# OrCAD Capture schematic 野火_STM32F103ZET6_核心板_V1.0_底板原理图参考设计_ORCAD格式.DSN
size A4; title: 野火_STM32F103ZET6底板参考设计_原理图; rev: V1.0; note: MCU_B2B
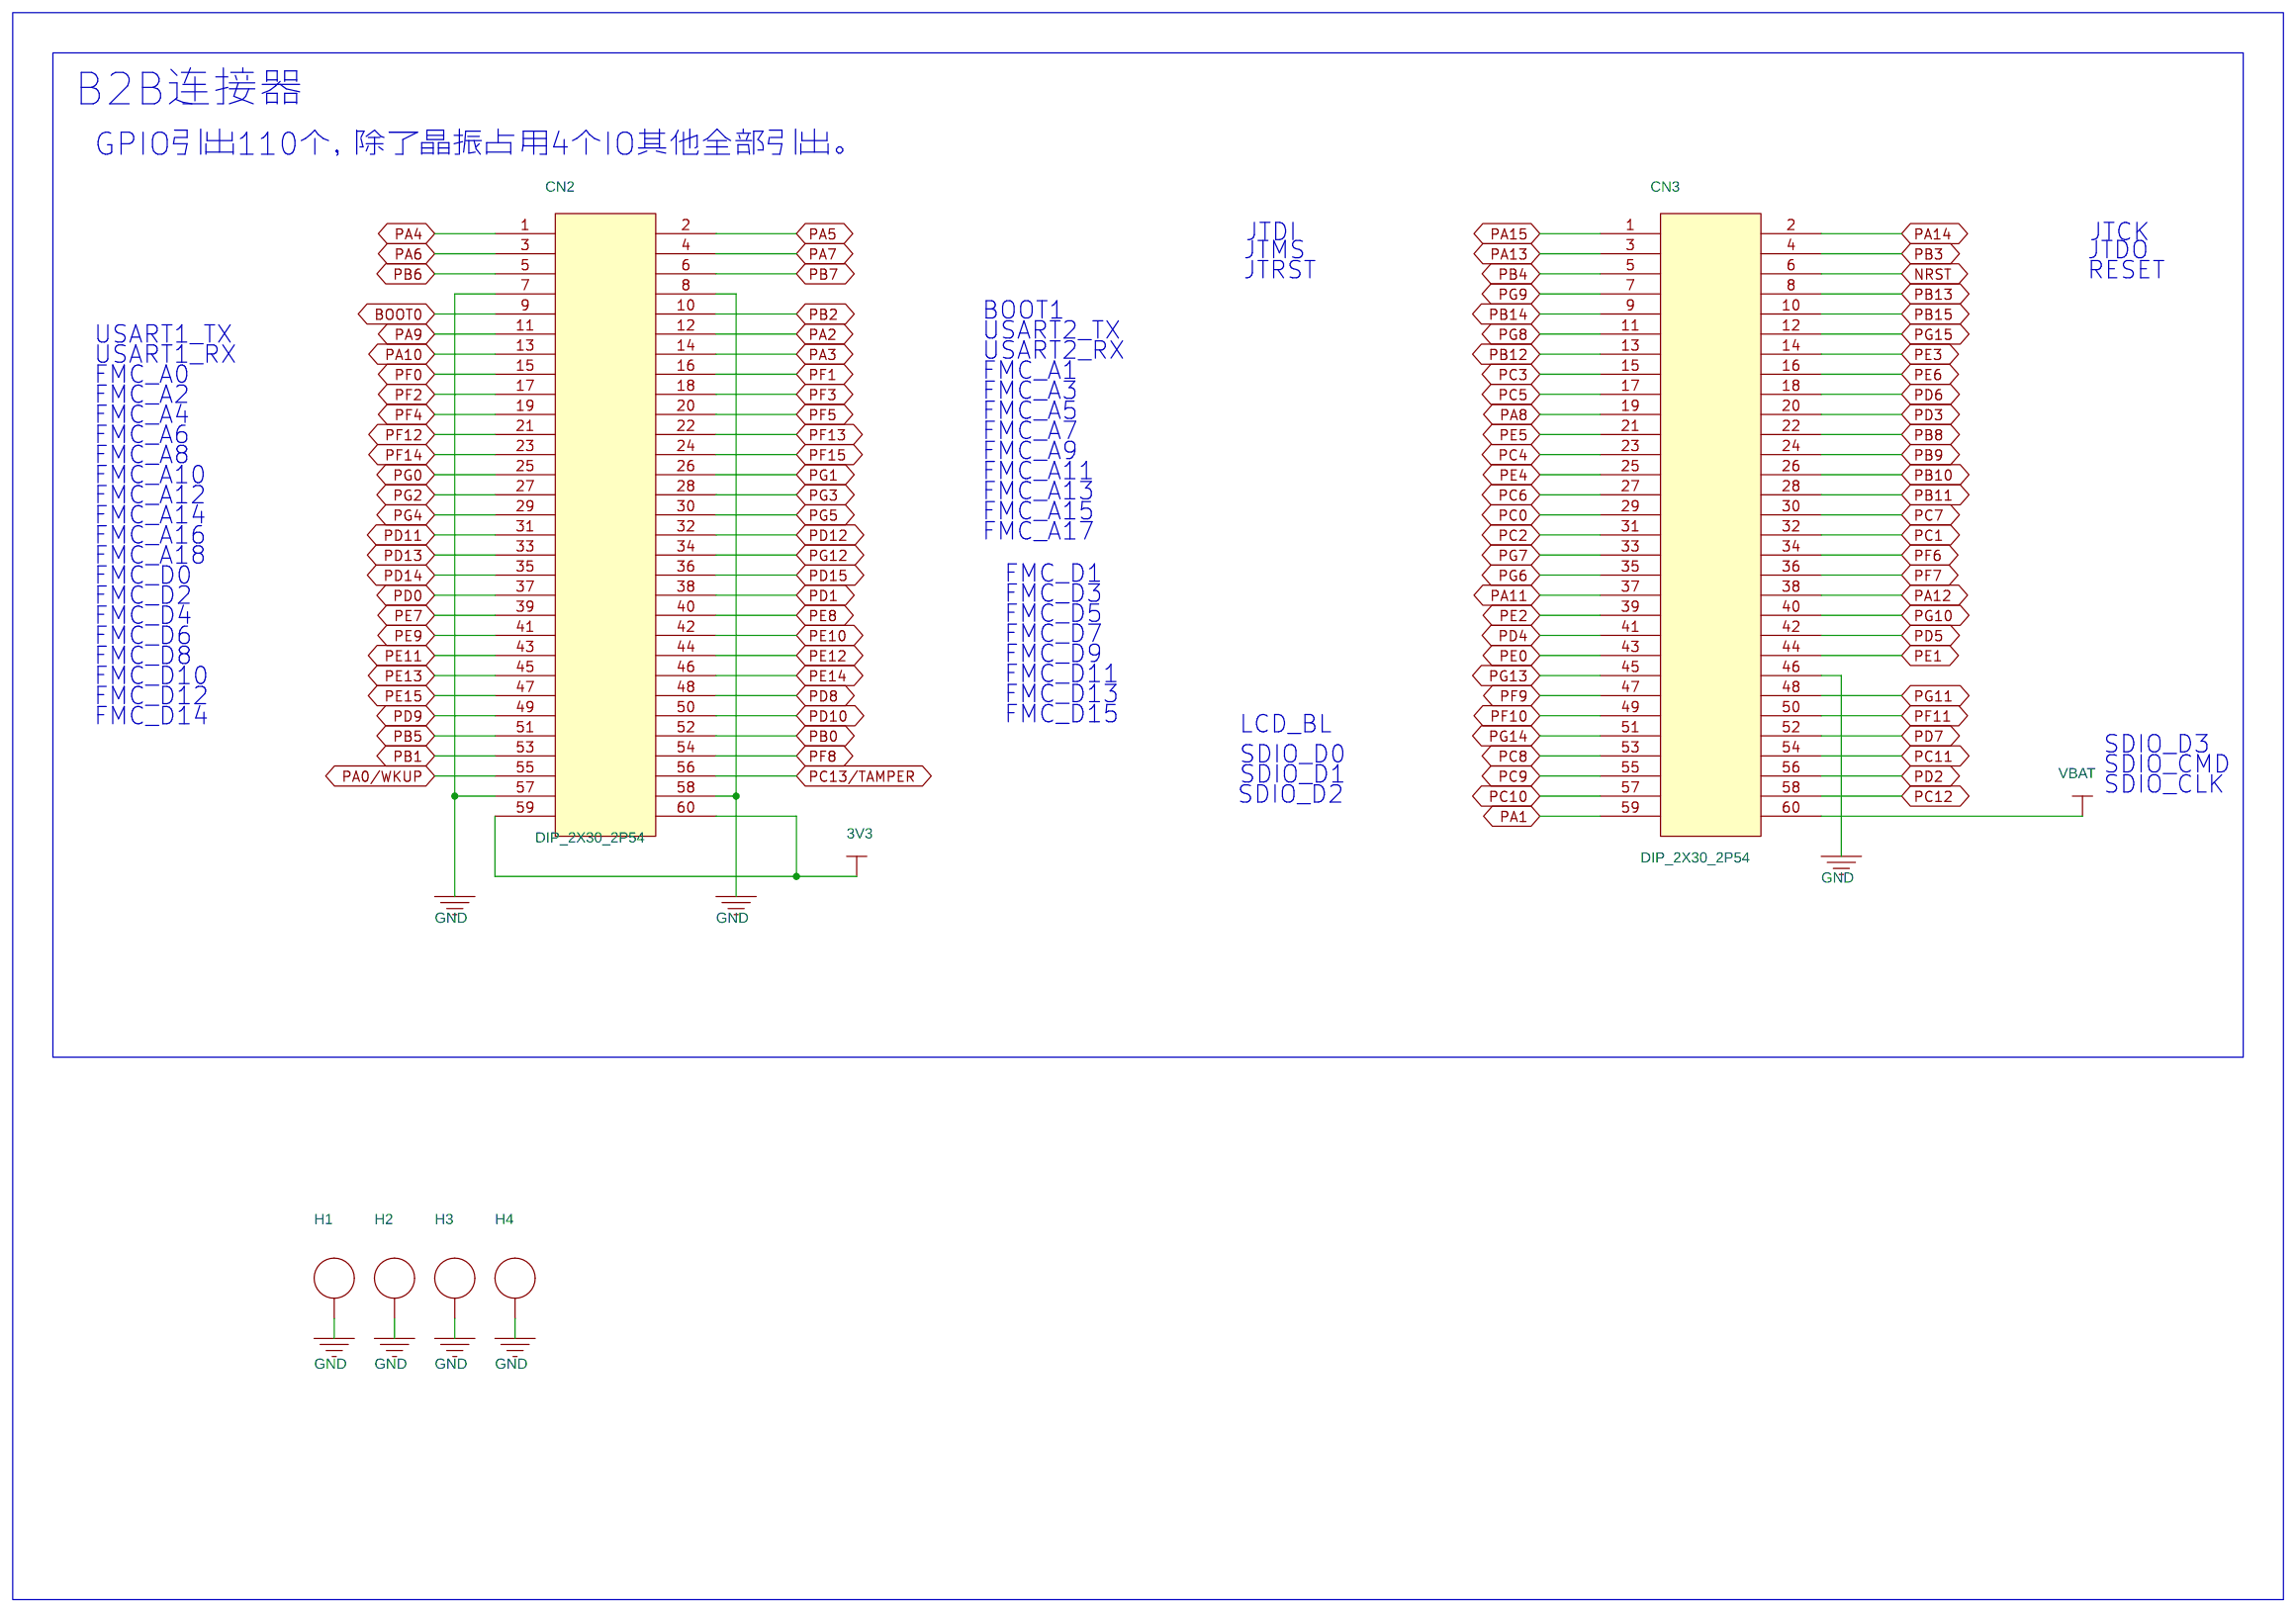
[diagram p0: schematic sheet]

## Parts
CN2  DIP_2X30_2P54  [DIP-2X302P54]
CN3  DIP_2X30_2P54  [DIP-2X302P54]
H1  3.0mm  [t3-5p5]
H2  3.0mm  [t3-5p5]
H3  3.0mm  [t3-5p5]
H4  3.0mm  [t3-5p5]

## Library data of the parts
CN2 CN3 = DIP_2X40_0
H1-H4 = SPACER_0: FASTENER, STANDOFF 4.5MMX3.53XM3.0X0.5 ROUND THR .635"L BRASS; AGILE_PN: 280-76498; ASSY_OPT: DNP; CAD_APPROVED: Yes; HEIGHT: 16.13MM; MFG_NAME01: UNICORP; MFG_PN01: MSS251-R-1-A-16; ROHS: Yes

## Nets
3V3: CN2.59 CN2.60
GND: CN2.7 CN2.8 CN2.57 CN2.58 CN3.46 H1.1(NC) H2.1(NC) H3.1(NC) H4.1(NC)
VBAT: CN3.60
BOOT0: CN2.9
NRST: CN3.6
PA0/WKUP: CN2.55
PA1: CN3.59
PA2: CN2.12
PA3: CN2.14
PA4: CN2.1
PA5: CN2.2
PA6: CN2.3
PA7: CN2.4
PA8: CN3.19
PA9: CN2.11
PA10: CN2.13
PA11: CN3.37
PA12: CN3.38
PA13: CN3.3
PA14: CN3.2
PA15: CN3.1
PB0: CN2.52
PB1: CN2.53
PB2: CN2.10
PB3: CN3.4
PB4: CN3.5
PB5: CN2.51
PB6: CN2.5
PB7: CN2.6
PB8: CN3.22
PB9: CN3.24
PB10: CN3.26
PB11: CN3.28
PB12: CN3.13
PB13: CN3.8
PB14: CN3.9
PB15: CN3.10
PC0: CN3.29
PC1: CN3.32
PC2: CN3.31
PC3: CN3.15
PC4: CN3.23
PC5: CN3.17
PC6: CN3.27
PC7: CN3.30
PC8: CN3.53
PC9: CN3.55
PC10: CN3.57
PC11: CN3.54
PC12: CN3.58
PC13/TAMPER: CN2.56
PD0: CN2.37
PD1: CN2.38
PD2: CN3.56
PD3: CN3.20
PD4: CN3.41
PD5: CN3.42
PD6: CN3.18
PD7: CN3.52
PD8: CN2.48
PD9: CN2.49
PD10: CN2.50
PD11: CN2.31
PD12: CN2.32
PD13: CN2.33
PD14: CN2.35
PD15: CN2.36
PE0: CN3.43
PE1: CN3.44
PE2: CN3.39
PE3: CN3.14
PE4: CN3.25
PE5: CN3.21
PE6: CN3.16
PE7: CN2.39
PE8: CN2.40
PE9: CN2.41
PE10: CN2.42
PE11: CN2.43
PE12: CN2.44
PE13: CN2.45
PE14: CN2.46
PE15: CN2.47
PF0: CN2.15
PF1: CN2.16
PF2: CN2.17
PF3: CN2.18
PF4: CN2.19
PF5: CN2.20
PF6: CN3.34
PF7: CN3.36
PF8: CN2.54
PF9: CN3.47
PF10: CN3.49
PF11: CN3.50
PF12: CN2.21
PF13: CN2.22
PF14: CN2.23
PF15: CN2.24
PG0: CN2.25
PG1: CN2.26
PG2: CN2.27
PG3: CN2.28
PG4: CN2.29
PG5: CN2.30
PG6: CN3.35
PG7: CN3.33
PG8: CN3.11
PG9: CN3.7
PG10: CN3.40
PG11: CN3.48
PG12: CN2.34
PG13: CN3.45
PG14: CN3.51
PG15: CN3.12

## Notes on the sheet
- B2B连接器
- GPIO引出110个，除了晶振占用4个IO其他全部引出。
- JTDI
- JTCK
- JTMS
- JTDO
- JTRST
- RESET
- BOOT1
- USART1_TX
- USART2_TX
- USART1_RX
- USART2_RX
- FMC_A0
- FMC_A1
- FMC_A2
- FMC_A3
- FMC_A4
- FMC_A5
- FMC_A7
- FMC_A6
- FMC_A8
- FMC_A9
- FMC_A10
- FMC_A11
- FMC_A12
- FMC_A13
- FMC_A14
- FMC_A15
- FMC_A16
- FMC_A17
- FMC_A18
- FMC_D0
- FMC_D1
- FMC_D2
- FMC_D3
- FMC_D4
- FMC_D5
- FMC_D6
- FMC_D7
- FMC_D8
- FMC_D9
- FMC_D10
- FMC_D11
- FMC_D13
- FMC_D12
- FMC_D14
- FMC_D15
- LCD_BL
- SDIO_D0
- SDIO_CMD
- SDIO_D3
- SDIO_D1
- SDIO_CLK
- SDIO_D2
